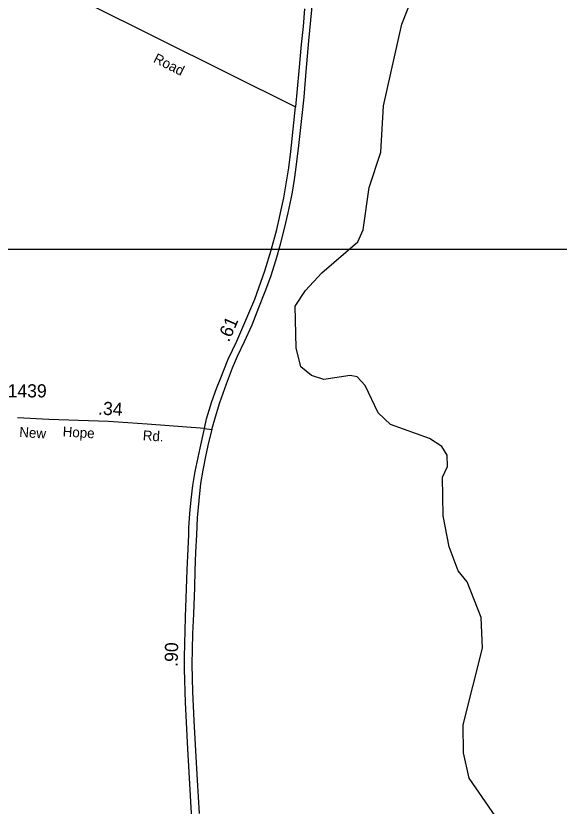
# Model space of a CAD drawing. Extents: x 2532689 to 2764727, y 536648 to 732970.
# Drawn here: x 2572716 to 2577883, y 675305 to 682821 of the extents above; entities that cross this region are included whole.
import ezdxf

# ---------------------------------------------------------------- set-up
doc = ezdxf.new("R2010")
doc.units = 0
for name, color, linetype in [('Exist Hydrographic Creek Single Shore', 7, 'Continuous'), ('Exist Road Primary US Divided Attributed', 7, 'Continuous'), ('Exist Road Primary US Mileage Hundredths English Label', 7, 'Continuous'), ('Exist Road Secondary Mileage Hundredths English Label', 7, 'Continuous'), ('Exist Road Secondary Type 51 Attributed', 7, 'Continuous'), ('Exist Road Secondary Type 51 Label', 7, 'Continuous'), ('Exist Road Secondary Type 51 Number Label', 7, 'Continuous'), ('Map Preparation Inset Cut Line', 7, 'Continuous')]:
    doc.layers.add(name, color=color, linetype=linetype)

msp = doc.modelspace()

# ---------------------------------------------------------------- linework, layer by layer
at = {"layer": 'Exist Hydrographic Creek Single Shore'}
msp.add_lwpolyline([(2577337, 675121.6), (2577028.8, 675572), (2576973.8, 675812.7), (2576968.9, 676078.5), (2577153.8, 676808.2), (2577139.9, 677099.8), (2577008.9, 677439.3), (2576922.7, 677544.2), (2576835.8, 677770.4), (2576779.8, 678066.9), (2576772.9, 678434.3), (2576820.8, 678534.8), (2576818.8, 678643), (2576766.7, 678726.3), (2576648.8, 678800.3), (2576278.9, 678933.1), (2576160.8, 679046.5), (2576038.8, 679304.2), (2575961.9, 679386.4), (2575894.8, 679400.1), (2575645.7, 679363.8), (2575528.8, 679401.7), (2575426.7, 679482.9), (2575381.8, 679665), (2575373.8, 680058.6), (2575470.8, 680210.3), (2575625.8, 680377.4), (2575969.7, 680670.4), (2576017.9, 680787.3), (2576076.7, 681187), (2576186.8, 681523), (2576211.8, 681964), (2576387.8, 682742.6), (2576602.7, 683289.7)], dxfattribs=at)
at = {"layer": 'Exist Road Primary US Divided Attributed'}
for points in [[(2574579.1, 678886.6), (2574614.4, 679007.3), (2574656.1, 679143.1), (2574718.2, 679321.3), (2574777.8, 679472.5), (2574825.1, 679584.7), (2574889.8, 679724.6), (2574962.7, 679883.9), (2575027.9, 680047.3), (2575088, 680198.4), (2575139.9, 680341.3), (2575192.3, 680502.7), (2575232.5, 680648.2), (2575272.6, 680799.3), (2575306.6, 680947.8), (2575335.8, 681080.8), (2575347.3, 681142.4), (2575367.5, 681265.4), (2575379.2, 681354.9), (2575405.8, 681589.1), (2575439.1, 681874.5), (2575458.8, 682048.6), (2575477.7, 682291.6), (2575501.2, 682582), (2575539.8, 682980.7)], [(2575461.8, 682887.3), (2575447.8, 682717.8), (2575430.6, 682548.3), (2575408.1, 682297.2), (2575374.3, 681955.1)], [(2574510.7, 678895.5), (2574528.8, 678987.1), (2574580.9, 679151.8), (2574623.9, 679275.6), (2574659.7, 679363.5), (2574734.9, 679556.3), (2574817.2, 679725.9), (2574989.8, 680126.9), (2575083.1, 680394.5), (2575144.5, 680590.9), (2575198.7, 680788.3), (2575266.2, 681090), (2575313.8, 681373.8), (2575331.9, 681530.8), (2575374.3, 681955.1)], [(2574535.7, 674143.9), (2574508.8, 674327.7), (2574473, 674527.2), (2574455.6, 674646.9), (2574427, 674813.6), (2574410.6, 674940.4), (2574389.4, 675180.8), (2574351.9, 675849.6), (2574329.5, 676291.5), (2574321, 676607.9), (2574319.6, 676723.2), (2574328.1, 677103.1), (2574346.3, 677553.7), (2574360.7, 677885.9), (2574362.5, 677953), (2574370.2, 678088.9), (2574383.5, 678218), (2574399.9, 678353), (2574422.4, 678486), (2574469, 678710), (2574510.7, 678895.5)], [(2574579.1, 678886.6), (2574549.5, 678764.9), (2574521.6, 678644.5), (2574494.8, 678501.6), (2574472.5, 678375), (2574456.4, 678212.6), (2574439.8, 678047.7), (2574433.4, 677885.8), (2574425, 677720.4), (2574419.6, 677546.8), (2574413.7, 677385.9), (2574405, 677133.8), (2574395.5, 676944.3), (2574390.9, 676650.8), (2574397.1, 676391.5), (2574409.9, 676120), (2574425.7, 675832), (2574441.6, 675551.3), (2574458.4, 675235.2)]]:
    msp.add_lwpolyline(points, dxfattribs=at)
at = {"layer": 'Exist Road Secondary Type 51 Attributed'}
msp.add_line((2574510.7, 678895.5), (2574579.1, 678886.6), dxfattribs=at)
for points in [[(2572733.3, 683274.1), (2575374.3, 681955.1)], [(2574510.7, 678895.5), (2573965.7, 678938.5), (2573598.5, 678964.1), (2573502.4, 678967.2), (2573030.9, 678982.5), (2572733.2, 678997.9)]]:
    msp.add_lwpolyline(points, dxfattribs=at)
at = {"layer": 'Map Preparation Inset Cut Line'}
msp.add_lwpolyline([(2549570.7, 680600.4), (2610045.1, 680600.4), (2610045.1, 636351.9), (2549570.7, 636351.9)], close=True, dxfattribs=at)

# ---------------------------------------------------------------- texts
at = {"layer": 'Exist Road Primary US Mileage Hundredths English Label'}
for s, rotation, p in [('.61', 66.71236, (2574743, 679711.6)), ('.90', 88.72581, (2574255, 676629.3))]:
    msp.add_text(s, height=125, rotation=rotation, dxfattribs=at).set_placement(p)
at = {"layer": 'Exist Road Secondary Mileage Hundredths English Label'}
msp.add_text('.34', height=125, rotation=356.74802, dxfattribs=at).set_placement((2573495.9, 679029.5))
at = {"layer": 'Exist Road Secondary Type 51 Label'}
for s, rotation, p in [('Road', 333.36338, (2574016.4, 682384.1)), ('New', 356.27119, (2572746.7, 678816.8)), ('Hope', 356.45426, (2573159.3, 678821.4)), ('Rd.', 356.45426, (2573921.2, 678784.3))]:
    msp.add_text(s, height=95, rotation=rotation, dxfattribs=at).set_placement(p)
at = {"layer": 'Exist Road Secondary Type 51 Number Label'}
msp.add_text('1439', height=125, rotation=359.94, dxfattribs=at).set_placement((2572637.8, 679192.4))

doc.saveas('drawing.dxf')
